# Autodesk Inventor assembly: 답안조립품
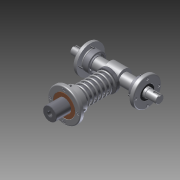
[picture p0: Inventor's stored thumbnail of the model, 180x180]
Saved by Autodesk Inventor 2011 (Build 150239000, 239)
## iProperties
Created: 2014-12
Part Number: 답안조립품
Document SubType Name: Assembly
Designer: user
Author: user
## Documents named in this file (13)
- D:\341225V1008\답안조립품.iam
- D:\341225V1008\본체.ipt
- D:\341225V1008\편심축.ipt
- D:\341225V1008\슬라이드.ipt
- D:\341225V1008\축 커버.ipt
- D:\341225V1008\슬라이드 커버.ipt
- D:\341225V1008\베어링 6205.ipt
- 베어링 6205.ipt
- D:\341225V1008\부시.ipt
- D:\341225V1008\오일실.ipt
- 오일실.ipt
- D:\341225V1008\M4x0.7.ipt
- D:\341225V1008\가변스프링.ipt
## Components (13 placed, 2 different names)
1. 가변스프링:1
2. M4x0.7:3
3. M4x0.7:4
4. M4x0.7:5
5. M4x0.7:6
6. M4x0.7:2
7. M4x0.7:7
8. M4x0.7:8
9. M4x0.7:9
10. M4x0.7:1
11. M4x0.7:10
12. M4x0.7:11
13. M4x0.7:12
